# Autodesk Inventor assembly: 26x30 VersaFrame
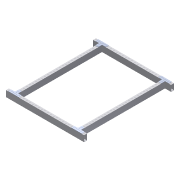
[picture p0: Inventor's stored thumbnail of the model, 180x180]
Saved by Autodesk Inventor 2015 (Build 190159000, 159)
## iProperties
Created: 2014-12
Part Number: 26x30 VersaFrame
Document SubType Name: Assembly
Designer: Nemo
Author: Nemo
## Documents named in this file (4)
- H:\Nemo\Documents\Robotics\CAD Files\COTS Parts\VersaFrame\26x30 Frame\26x30 VersaFrame 12-20-14.iam
- H:\Nemo\Documents\Robotics\CAD Files\COTS Parts\VersaFrame\26x30 Frame\VersaFrame End Rail 12-20-14.ipt
- H:\Nemo\Documents\Robotics\CAD Files\COTS Parts\VersaFrame\26x30 Frame\VersaFrame Side Rail 12-20-14.ipt
- H:\Nemo\Documents\Robotics\CAD Files\COTS Parts\VersaFrame\VersaFrame VersaChassis Gusset.ipt
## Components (8 placed, 4 different names)
1. VersaFrame End Rail: Front — Mate:1, Flush:1, Flush:2, Flush:3, Flush:5, Mate:2, Flush:6, Flush:8, Flush:9, Mate:6, Flush:14, Mate:7, Flush:16
2. VersaFrame End Rail: Back — Mate:1, Flush:2, Mate:3, Mate:4, Flush:10, Mate:5, Flush:13
3. VersaFrame Side Rail 12-20-14:1 — Flush:4, Flush:5, Mate:2, Mate:3, Flush:6, Flush:11, Flush:15
4. VersaFrame Side Rail 12-20-14:2 — Flush:7, Flush:8, Flush:9, Flush:12, Flush:17
5. VersaFrame VersaChassis Gusset:1 — Mate:7, Flush:16, Flush:17
6. VersaFrame VersaChassis Gusset:2 — Mate:6, Flush:14, Flush:15
7. VersaFrame VersaChassis Gusset:3 — Mate:5, Flush:12, Flush:13
8. VersaFrame VersaChassis Gusset:4 — Mate:4, Flush:10, Flush:11
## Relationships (24: Flush 17, Mate 7)
- Mate:1: VersaFrame End Rail: Front ↔ VersaFrame End Rail: Back
- Flush:1: VersaFrame End Rail: Front
- Flush:2: VersaFrame End Rail: Front ↔ VersaFrame End Rail: Back
- Flush:3: VersaFrame End Rail: Front
- Flush:4: VersaFrame Side Rail 12-20-14:1
- Flush:5: VersaFrame End Rail: Front ↔ VersaFrame Side Rail 12-20-14:1
- Mate:2: VersaFrame End Rail: Front ↔ VersaFrame Side Rail 12-20-14:1
- Mate:3: VersaFrame End Rail: Back ↔ VersaFrame Side Rail 12-20-14:1
- Flush:6: VersaFrame End Rail: Front ↔ VersaFrame Side Rail 12-20-14:1
- Flush:7: VersaFrame Side Rail 12-20-14:2
- Flush:8: VersaFrame End Rail: Front ↔ VersaFrame Side Rail 12-20-14:2
- Flush:9: VersaFrame End Rail: Front ↔ VersaFrame Side Rail 12-20-14:2
- Mate:4: VersaFrame End Rail: Back ↔ VersaFrame VersaChassis Gusset:4
- Flush:10: VersaFrame End Rail: Back ↔ VersaFrame VersaChassis Gusset:4
- Flush:11: VersaFrame Side Rail 12-20-14:1 ↔ VersaFrame VersaChassis Gusset:4
- Mate:5: VersaFrame End Rail: Back ↔ VersaFrame VersaChassis Gusset:3
- Flush:12: VersaFrame Side Rail 12-20-14:2 ↔ VersaFrame VersaChassis Gusset:3
- Flush:13: VersaFrame End Rail: Back ↔ VersaFrame VersaChassis Gusset:3
- Mate:6: VersaFrame End Rail: Front ↔ VersaFrame VersaChassis Gusset:2
- Flush:14: VersaFrame End Rail: Front ↔ VersaFrame VersaChassis Gusset:2
- Flush:15: VersaFrame Side Rail 12-20-14:1 ↔ VersaFrame VersaChassis Gusset:2
- Mate:7: VersaFrame End Rail: Front ↔ VersaFrame VersaChassis Gusset:1
- Flush:16: VersaFrame End Rail: Front ↔ VersaFrame VersaChassis Gusset:1
- Flush:17: VersaFrame Side Rail 12-20-14:2 ↔ VersaFrame VersaChassis Gusset:1
## Named parameters: SideRailOffset = 50.8 mm, CenterDrop = 3.175 mm
